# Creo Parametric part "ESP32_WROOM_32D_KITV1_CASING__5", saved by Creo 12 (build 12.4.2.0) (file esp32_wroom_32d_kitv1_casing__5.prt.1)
Units: Custom; MM, KILOGRAM, SECS

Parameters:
  PTC_WM_ITERATION = "0"
  PTC_WM_VERSION = "-.0"
  PTC_WM_LIFECYCLE_STATE = "In Work"
  PTC_WM_LIFECYCLE = "MO_CADDocument"
  PTC_WM_CREATED_BY = "Maximilian Roepper (Z0017RMS: MO)"
  PTC_WM_CREATED_ON = "18-Sep-26 11:36:42 AM"
  PTC_WM_MODIFIED_BY = "Maximilian Roepper (Z0017RMS: MO)"
  PTC_WM_MODIFIED_ON = "18-Sep-26 11:36:46 AM"
  PDMLINKNUMBER = "PDM000071455262"
  PTC_WM_NAME = "esp32_wroom_32d_kitv1_casing__5.prt"
  PTC_WM_NUMBER = "PDM000071455262"

Other parameters: WEIGHT, WEIGHT_FACTOR, WEIGHT_ADD, _MASS_TEMP, _DIFF_TEMP, MC_ERRORS, SUPPLIER

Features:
  1. coordinate system
  2. datum plane "PRT_YZ"
  3. datum plane "PRT_XY"
  4. datum plane "PRT_XZ"
  5. coordinate system
  6. datum axis
  7. datum axis
  8. datum axis
  9. coordinate system
  10. imported feature
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
Other named items: PRT, SIEMENS_MO, DRW_VIEW_ORG, PRT_X, PRT_Y, PRT_Z, CS0, ROUGH_GROB

Layers: 00_STD_CSYS-KSYS, 01_STD_PLANES-EBENEN, 02_STD_AXES-ACHSEN, 03_STD_CSYS-KSYS, 24_IMPORT_FEAT-IMPORT_KE

Surfaces: 6 plane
